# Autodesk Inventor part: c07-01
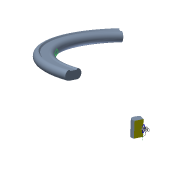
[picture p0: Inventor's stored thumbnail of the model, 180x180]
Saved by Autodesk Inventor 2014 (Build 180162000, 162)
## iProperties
Created: 2010-12
Part Number: c07-01
Document SubType Name: Modeling
Designer: Thom Tremblay
Density: 1 g/cm^3
Material: Generic
Appearance: Light Steel Blue
Author: Thom Tremblay
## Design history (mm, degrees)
sketch "Sketch2"
  geometry: L1 (0, 0)-(-11.43, 0); L2 (-11.43, 0)-(-11.43, 16.51); L3 (-11.43, 16.51)-(0, 16.51); L4 (0, 16.51)-(0, 0); L5 (-96.52, 66.04)-(-86.36, 66.04); L6 (-86.36, 76.2)-(-96.52, 76.2); L7 (-95.25, 74.93)-(-87.63, 74.93); L8 (-96.52, 76.2)-(-95.25, 74.93); L9 (-86.36, 76.2)-(-87.63, 74.93); A1 r 5.08 centre (-86.36, 71.12) between (-86.36, 66.04) and (-86.36, 76.2); A2 r 5.08 centre (-96.52, 71.12) between (-96.52, 76.2) and (-96.52, 66.04)
  constraints: 18 end point, 4 parallel, 4 point on circle, 4 tangent, 2 centre point, 2 horizontal, 2 perpendicular
  dimensions: "d6" = 16.51 distance of L1.end L2.end; "d7" = 22.86 diameter of L2 L4; "d10" = 5.08 radius of A1; "d11" = 20.32 dimension on A2 A1; "d12" = 3.81 distance from line of A1.centre L7; "d13" = 7.62 distance of L7.start L7.end; "d14" = 76.2 distance from line of L6.end L1; "d15" = 203.2 dimension on A2 L4
revolve "Revolution1" sketch "Sketch2" stored, may be unused: angle "d16" = 120 deg
sketch "Plane Sketch 1"
  geometry: L1 (-48.26, -83.589)-(-43.18, -74.79) reference; L2 (-48.26, 83.589)-(-43.18, 74.79) reference; L3 (0, 0)-(-89.708, 15.818); L4 (0, 0)-(-86.36, 0); A1 r 86.36 centre (0, 0) between (-43.18, 74.79) and (-43.18, -74.79) reference; A2 r 96.52 centre (0, 0) between (-48.26, 83.589) and (-48.26, -83.589) reference; 1 further point
  constraints: 4 end point, 1 point on circle
  dimensions: "d65" = 10 deg angle of L3 L4; "d66" = 91.09202 distance of L3.start L3.end
workplane "Work Plane2"
sketch "Sketch10"
  geometry: L1 (-8.89, 5.08)-(8.89, 5.08); L2 (-8.89, 2.54)-(8.89, 2.54); L3 (8.89, 7.62)-(-8.89, 7.62); A1 r 2.54 centre (-8.89, 5.08) between (-8.89, 7.62) and (-8.89, 2.54); A2 r 2.54 centre (8.89, 5.08) between (8.89, 2.54) and (8.89, 7.62); 2 further points
  constraints: 8 end point, 4 point on circle, 4 tangent, 2 centre point, 1 midpoint, 1 parallel, 1 vertical alignment
  dimensions: "d67" = 71.12 distance from line of L1 point (0, -66.04); "d68" = 17.78 distance of L3.start L3.end; "d69" = 2.54 radius of A2
sketch "Loft Sketch 1"
  node "Project from Sketch10"
sketch "Loft Sketch 2"
  geometry: C1 r 3.81 at (0, 7.62); 1 further point
  constraints: 1 centre point, 1 vertical alignment
  dimensions: "d63" = 7.62 diameter of C1; "d64" = 7.62 distance of point (0, 0) C1.centre
body "Solid1"
